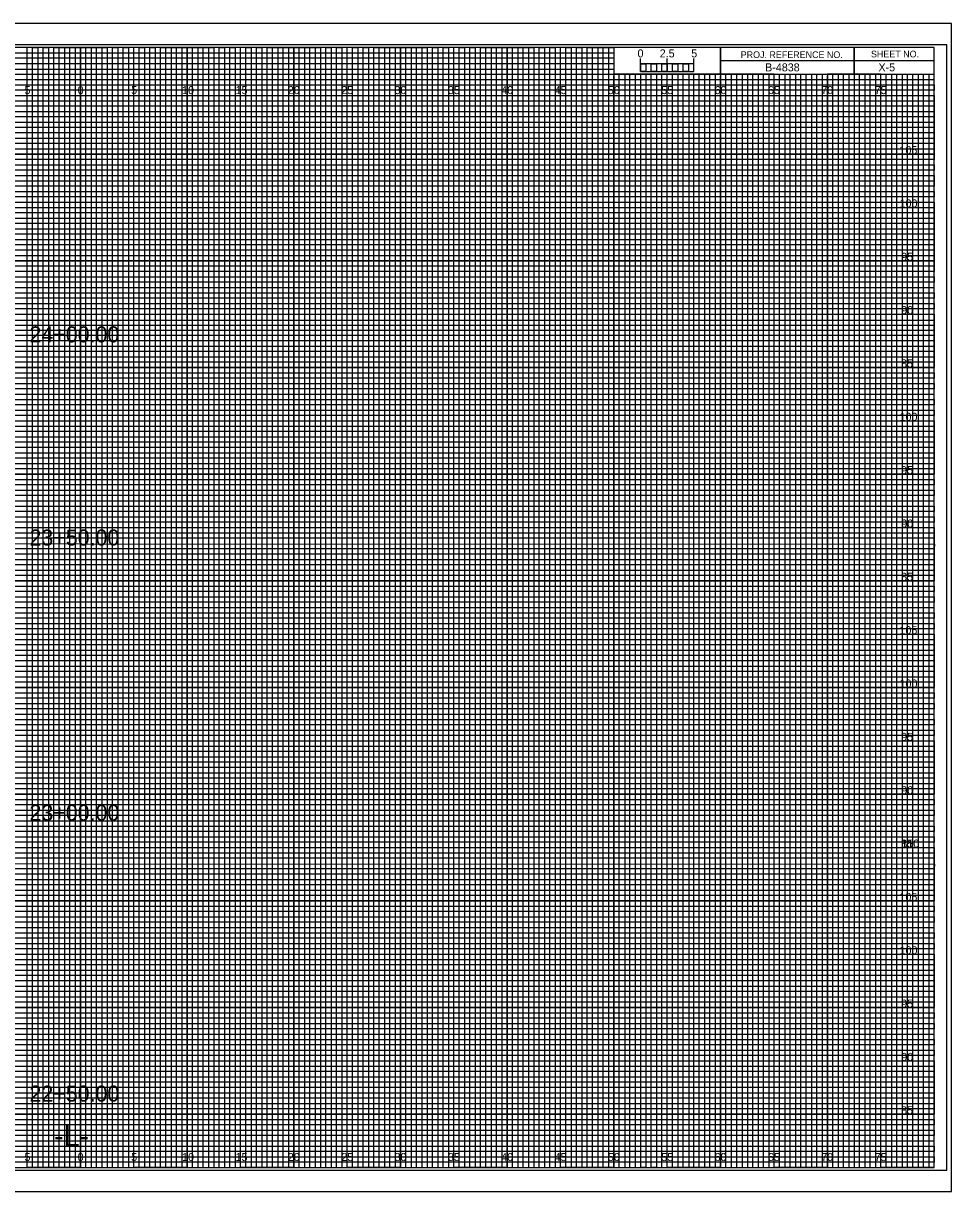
# Model space of a CAD drawing. Extents: x -7 to 182, y -2 to 1647.
# Drawn here: x 74.6 to 161.7, y 327.7 to 437.2 of the extents above; entities that cross this region are included whole.
import ezdxf

# ---------------------------------------------------------------- set-up
doc = ezdxf.new("R2010")
doc.units = 0
for name, color, linetype in [('Exist CMT Pavement', 7, 'Continuous'), ('Exist Cross Section Cell', 7, 'Continuous'), ('Exist XS Ground Line', 7, 'Continuous'), ('Prop CMT Pvmt Course 1', 7, 'Continuous'), ('Prop CMT Pvmt Course 2', 7, 'Continuous'), ('Prop CMT Pvmt Course 2 Wedge', 7, 'Continuous'), ('Prop CMT Pvmt Course 3', 7, 'Continuous'), ('Prop CMT Pvmt Surface', 7, 'Continuous'), ('Prop CMT Pvmt Surface Shoulder', 7, 'Continuous'), ('Prop CMT Pvmt Wedge Surface 1', 7, 'Continuous'), ('Prop CMT Pvmt Wedge Surface 2', 7, 'Continuous'), ('Prop CMT Pvmt Wedge Surface 3', 7, 'Continuous'), ('Prop CMT Shld Paved Course 1', 7, 'Continuous'), ('Prop CMT Shld Paved Course 2', 7, 'Continuous'), ('Prop CMT Shld Paved Course 3', 7, 'Continuous'), ('Prop CMT Slope Grass', 7, 'Continuous'), ('Prop CMT Subgrade Earthwork', 7, 'Continuous')]:
    doc.layers.add(name, color=color, linetype=linetype)

msp = doc.modelspace()

# ---------------------------------------------------------------- linework, layer by layer
at = {"layer": 'Exist XS Ground Line'}
for p, q in [((75, 435), (70, 435)), ((75, 330), (75, 435)), ((85, 435), (80, 435)), ((80, 435), (80, 330)), ((85, 330), (85, 435)), ((95, 435), (90, 435)), ((90, 435), (90, 330)), ((95, 330), (95, 435)), ((105, 435), (100, 435)), ((100, 435), (100, 330)), ((105, 330), (105, 435)), ((115, 435), (110, 435)), ((110, 435), (110, 330)), ((115, 330), (115, 435)), ((125, 435), (120, 435)), ((120, 435), (120, 330)), ((125, 330), (125, 435)), ((130, 435), (130, 330)), ((135, 330), (135, 432.5)), ((145, 432.5), (140, 432.5)), ((140, 432.5), (140, 330)), ((145, 330), (145, 432.5)), ((155, 432.5), (150, 432.5)), ((150, 432.5), (150, 330)), ((155, 330), (155, 432.5)), ((80, 330), (75, 330)), ((90, 330), (85, 330)), ((100, 330), (95, 330)), ((110, 330), (105, 330)), ((120, 330), (115, 330)), ((130, 330), (125, 330)), ((140, 330), (135, 330)), ((150, 330), (145, 330)), ((160, 330), (155, 330)), ((160, 330), (160, 330))]:
    msp.add_line(p, q, dxfattribs=at)
for points in [[(0, 430), (160, 430), (160, 425), (0, 425)], [(0, 420), (160, 420), (160, 415), (0, 415)], [(0, 410), (160, 410), (160, 405), (0, 405)], [(0, 400), (160, 400), (160, 395), (0, 395)], [(0, 390), (160, 390), (160, 385), (0, 385)], [(0, 380), (160, 380), (160, 375), (0, 375)], [(0, 370), (160, 370), (160, 365), (0, 365)], [(0, 360), (160, 360), (160, 355), (0, 355)], [(0, 350), (160, 350), (160, 345), (0, 345)], [(0, 340), (160, 340), (160, 335), (0, 335)]]:
    msp.add_lwpolyline(points, dxfattribs=at)
at = {"layer": 'Prop CMT Pvmt Course 2'}
for p, q in [((132.5, 432.75), (132.5, 433.95)), ((132.5, 433.45), (132.5, 433.95)), ((135, 432.75), (135, 433.95)), ((137.5, 432.75), (137.5, 433.95)), ((137.5, 433.45), (137.5, 433.95))]:
    msp.add_line(p, q, dxfattribs=at)
for points in [[(137.5, 433.45), (132.5, 433.45), (132.5, 432.75), (137.5, 432.75)], [(132.5, 433.45), (133, 433.45), (133, 432.75), (132.5, 432.75)], [(133.5, 433.45), (134, 433.45), (134, 432.75), (133.5, 432.75)], [(134.5, 433.45), (135, 433.45), (135, 432.75), (134.5, 432.75)], [(135.5, 433.45), (136, 433.45), (136, 432.75), (135.5, 432.75)], [(136.5, 433.45), (137, 433.45), (137, 432.75), (136.5, 432.75)]]:
    msp.add_lwpolyline(points, close=True, dxfattribs=at)
at = {"layer": 'Prop CMT Pvmt Course 3'}
msp.add_lwpolyline([(-6.7, 327.75), (161.65, 327.75), (161.65, 437.25), (-6.7, 437.25)], close=True, dxfattribs=at)
at = {"layer": 'Prop CMT Pvmt Wedge Surface 1'}
for p, q in [((0, 434.5), (130, 434.5)), ((130, 433.99), (0, 433.99)), ((130, 434.5), (130, 433.99)), ((0, 433.5), (130, 433.5)), ((130, 432.94), (0, 432.94)), ((130, 433.5), (130, 432.94)), ((0, 432), (160, 432))]:
    msp.add_line(p, q, dxfattribs=at)
for points in [[(0, 431.5), (135, 431.5), (160, 431.5), (160, 431), (0, 431)], [(0, 430.5), (160, 430.5), (160, 429.5), (0, 429.5)], [(0, 429), (160, 429), (160, 428.5), (0, 428.49)], [(0, 428), (160, 428), (160, 427), (0, 427)], [(0, 426.5), (160, 426.5), (160, 426), (0, 426)], [(0, 425.5), (160, 425.5), (160, 424.5), (0, 424.5)], [(0, 424), (160, 424), (160, 423.5), (0, 423.5)], [(0, 423), (160, 423), (160, 422), (0, 422)], [(0, 421.5), (160, 421.5), (160, 421), (0, 421)], [(0, 420.5), (160, 420.5), (160, 419.5), (0, 419.5)], [(0, 419), (160, 419), (160, 418.5), (0, 418.5)], [(0, 418), (160, 418), (160, 416.98), (160, 416.5), (160, 416), (0, 416)], [(0, 417), (160, 417), (160, 416.5), (0, 416.5)], [(0, 415.5), (160, 415.5), (160, 414.5), (0, 414.51)], [(0, 414.51), (160, 414.5), (160, 414), (0, 414)], [(0, 413.5), (160, 413.5), (160, 413), (0, 413)], [(0, 412), (160, 412), (160, 411.5), (0, 411.5)], [(0, 411), (160, 411), (160, 410.5), (0, 410.5)], [(-0.04, 409.44), (160, 409.44), (160, 408.94), (-0.04, 408.94)], [(0, 408.5), (160, 408.5), (160, 408), (0, 408)], [(0, 407), (160, 407), (160, 406.5), (0, 406.5)], [(0, 406), (160, 406), (160, 405.5), (0, 405.5)], [(0, 404.5), (160, 404.5), (160, 404), (0, 404)], [(0, 403.5), (160, 403.5), (160, 403), (0, 403)], [(0, 402), (160, 402), (160, 401.5), (0, 401.5)], [(0, 401), (160, 401), (160, 400.5), (0, 400.5)], [(0, 399.5), (160, 399.5), (160, 398.99), (0, 399)], [(0, 398.5), (160, 398.5), (160, 398), (0, 398)], [(0, 397), (160, 397), (160, 396.5), (0, 396.5)], [(0, 396), (160, 396), (160, 395.5), (0, 395.5)], [(0, 394.5), (160, 394.5), (160, 394), (0, 394)], [(0, 393.5), (160, 393.5), (160, 393), (0, 393)], [(0, 392), (160, 392), (160, 391.5), (0, 391.5)], [(0, 391), (160, 391), (160, 390.5), (0, 390.5)], [(0, 389.5), (160, 389.5), (160, 389), (0, 389)], [(0, 388.5), (160.03, 388.45), (160, 388), (0, 388)], [(0, 387), (160, 387), (160, 386.5), (0, 386.5)], [(0, 386), (160, 386), (160, 385.5), (0, 385.5)], [(0, 384.5), (160, 384.5), (160, 384), (0, 384)], [(0, 383.5), (160, 383.5), (160, 383), (0, 383)], [(0, 382), (160, 382), (160, 381.5), (0, 381.5)], [(0, 381), (160, 381), (160, 380.5), (0, 380.5)], [(0, 379.5), (160, 379.5), (160, 379), (0, 379)], [(0, 378.5), (160, 378.5), (160, 378), (0, 378)], [(0, 377), (160, 377), (160, 376.5), (0, 376.5)], [(0, 376), (160, 376), (160, 375.5), (0, 375.5)], [(0, 374.5), (160, 374.5), (160, 374), (0, 374)], [(0, 373.5), (160, 373.5), (160, 373), (0, 373)], [(0, 372), (160, 372), (160, 371.5), (0, 371.5)], [(0, 371), (160, 371), (160, 370.5), (0, 370.5)], [(0, 369.5), (160, 369.5), (160, 368.99), (0, 369)], [(0, 368.5), (160, 368.5), (160, 368), (0, 368)], [(0, 367), (160, 367), (160, 366.5), (0, 366.5)], [(0, 366), (160, 366), (160, 365.5), (0, 365.5)], [(0, 364.5), (160, 364.5), (160, 364), (0, 364)], [(0, 363.5), (160, 363.5), (160, 363), (0, 363)], [(0, 362), (160, 362), (160, 361.5), (0, 361.5)], [(0, 361), (160, 361), (160, 360.5), (0, 360.5)], [(0, 359.5), (160, 359.5), (160, 359), (0, 359)], [(0, 358.5), (160.03, 358.45), (160, 358), (0, 358)], [(0, 357), (160, 357), (160, 356.5), (0, 356.5)], [(0, 356), (160, 356), (160, 355.5), (0, 355.5)], [(0, 354.5), (160, 354.5), (160, 354), (0, 354)], [(0, 353.5), (160, 353.5), (160, 353), (0, 353)], [(0, 352), (160, 352), (160, 351.5), (0, 351.5)], [(0, 351), (160, 351), (160, 350.5), (0, 350.5)], [(0, 349.5), (160, 349.5), (160, 349), (0, 349)], [(0, 348.5), (160, 348.5), (160, 348), (0, 348)], [(0, 347), (160, 347), (160, 346.5), (0, 346.5)], [(0, 346), (160, 346), (160, 345.5), (0, 345.5)], [(0, 344.5), (160, 344.5), (160, 344), (0, 344)], [(0, 343.5), (160, 343.5), (160, 343), (0, 343)], [(0, 342), (160, 342), (160, 341.5), (0, 341.5)], [(0, 341), (160, 341), (160, 340.5), (0, 340.5)], [(0, 339.5), (160, 339.5), (160, 339), (0, 339)], [(0, 338.5), (160, 338.5), (160, 338), (0, 338)], [(0, 337), (160, 337), (160, 336.5), (0, 336.5)], [(0, 336), (160, 336), (160, 335.5), (0, 335.5)], [(0, 334.5), (160, 334.5), (160, 334), (0, 334)], [(0, 333.5), (160, 333.5), (160, 333), (0, 333)], [(0, 332), (160, 332), (160, 331.5), (0, 331.5)], [(0, 331), (160, 331), (160, 330.5), (0, 330.5)]]:
    msp.add_lwpolyline(points, dxfattribs=at)
at = {"layer": 'Prop CMT Pvmt Wedge Surface 2'}
for p, q in [((152.5, 435), (152.5, 432.5)), ((152.5, 432.5), (152.5, 435)), ((160, 433.75), (140, 433.75)), ((140, 433.75), (140, 432.5)), ((140, 432.5), (160, 432.5))]:
    msp.add_line(p, q, dxfattribs=at)
for points in [[(160, 435), (0, 435), (0, 330), (160, 330)], [(140, 435), (130, 435), (130, 432.51), (140, 432.51)], [(160, 435), (140, 435), (140, 432.5), (160, 432.5)]]:
    msp.add_lwpolyline(points, close=True, dxfattribs=at)
at = {"layer": 'Prop CMT Pvmt Wedge Surface 3'}
for p, q in [((133.5, 432.5), (133, 432.5)), ((133, 432.5), (133, 330)), ((133.5, 330), (133.5, 432.5)), ((134.5, 432.5), (134, 432.5)), ((134, 432.5), (134, 330)), ((134.5, 330), (134.5, 432.5)), ((133, 330), (132.5, 330)), ((134, 330), (133.5, 330))]:
    msp.add_line(p, q, dxfattribs=at)
for points in [[(75, 330), (75.5, 330), (75.5, 435), (76, 435), (76, 330)], [(76, 330), (76.5, 330), (76.5, 435), (77, 435), (77, 330)], [(77.5, 330), (78, 330), (78, 435), (78.5, 435), (78.5, 330)], [(78.5, 330), (79, 330), (79, 435), (79.5, 435), (79.5, 330)], [(80, 330), (80.5, 330), (80.5, 435), (81, 435), (81, 330)], [(81, 330), (81.5, 330), (81.5, 435), (82, 435), (82, 330)], [(82.5, 330), (83, 330), (83, 435), (83.5, 435), (83.5, 330)], [(83.5, 330), (84, 330), (84, 435), (84.5, 435), (84.5, 330)], [(85, 330), (85.5, 330), (85.5, 435), (86, 435), (86, 330)], [(86, 330), (86.5, 330), (86.5, 435), (87, 435), (87, 330)], [(87.5, 330), (88, 330), (88, 435), (88.5, 435), (88.5, 330)], [(88.5, 330), (89, 330), (89, 435), (89.5, 435), (89.5, 330)], [(90, 330), (90.5, 330), (90.5, 435), (91, 435), (91, 330)], [(91, 330), (91.5, 330), (91.5, 435), (92, 435), (92, 330)], [(92.5, 330), (93, 330), (93, 435), (93.5, 435), (93.5, 330)], [(93.5, 330), (94, 330), (94, 435), (94.5, 435), (94.5, 330)], [(95, 330), (95.5, 330), (95.5, 435), (96, 435), (96, 330)], [(96, 330), (96.5, 330), (96.5, 435), (97, 435), (97, 330)], [(97.5, 330), (98, 330), (98, 435), (98.5, 435), (98.5, 330)], [(98.5, 330), (99, 330), (99, 435), (99.5, 435), (99.5, 330)], [(100, 330), (100.5, 330), (100.5, 435), (101, 435), (101, 330)], [(101, 330), (101.5, 330), (101.5, 435), (102, 435), (102, 330)], [(102.5, 330), (103, 330), (103, 435), (103.5, 435), (103.5, 330)], [(103.5, 330), (104, 330), (104, 435), (104.5, 435), (104.5, 330)], [(105, 330), (105.5, 330), (105.5, 435), (106, 435), (106, 330)], [(106, 330), (106.5, 330), (106.5, 435), (107, 435), (107, 330)], [(107.5, 330), (108, 330), (108, 435), (108.5, 435), (108.5, 330)], [(108.5, 330), (109, 330), (109, 435), (109.5, 435), (109.5, 330)], [(110, 330), (110.5, 330), (110.5, 435), (111, 435), (111, 330)], [(111, 330), (111.5, 330), (111.5, 435), (112, 435), (112, 330)], [(112.5, 330), (113, 330), (113, 435), (113.5, 435), (113.5, 330)], [(113.5, 330), (114, 330), (114, 435), (114.5, 435), (114.5, 330)], [(115, 330), (115.5, 330), (115.5, 435), (116, 435), (116, 330)], [(116, 330), (116.5, 330), (116.5, 435), (117, 435), (117, 330)], [(117.5, 330), (118, 330), (118, 435), (118.5, 435), (118.5, 330)], [(118.5, 330), (119, 330), (119, 435), (119.5, 435), (119.5, 330)], [(120, 330), (120.5, 330), (120.5, 435), (121, 435), (121, 330)], [(121, 330), (121.5, 330), (121.5, 435), (122, 435), (122, 330)], [(122.5, 330), (123, 330), (123, 435), (123.5, 435), (123.5, 330)], [(123.5, 330), (124, 330), (124, 435), (124.5, 435), (124.5, 330)], [(125, 330), (125.5, 330), (125.5, 435), (126, 435), (126, 330)], [(126, 330), (126.5, 330), (126.5, 435), (127, 435), (127, 330)], [(127.5, 330), (128, 330), (128, 435), (128.5, 435), (128.5, 330)], [(128.5, 330), (129, 330), (129, 435), (129.5, 435), (129.5, 330)], [(130, 330), (130.5, 330), (130.5, 432.5), (131.01, 432.5), (131.01, 330)], [(131, 330), (131.5, 330), (131.5, 432.5), (132, 432.5), (132, 330)], [(135, 330), (135.49, 330), (135.49, 432.5), (136, 432.5), (136, 330)], [(136, 330), (136.5, 330), (136.5, 432.5), (137.03, 432.5), (137.03, 330)], [(137.5, 330), (138, 330), (138, 432.5), (138.5, 432.5), (138.5, 330)], [(138.5, 330), (139, 330), (139, 432.5), (139.5, 432.5), (139.5, 330)], [(140, 330), (140.5, 330), (140.5, 432.5), (141, 432.5), (141, 330)], [(141, 330), (141.5, 330), (141.5, 432.5), (142, 432.5), (142, 330)], [(142.5, 330), (143, 330), (143, 432.5), (143.5, 432.5), (143.5, 330)], [(143.5, 330), (144, 330), (144, 432.5), (144.5, 432.5), (144.5, 330)], [(145, 330), (145.5, 330), (145.5, 432.5), (146, 432.5), (146, 330)], [(146, 330), (146.5, 330), (146.5, 432.5), (147, 432.5), (147, 330)], [(147.5, 330), (148, 330), (148, 432.5), (148.5, 432.5), (148.5, 330)], [(148.5, 330), (149, 330), (149, 432.5), (149.5, 432.5), (149.5, 330)], [(150, 330), (150.5, 330), (150.5, 432.5), (151, 432.5), (151, 330)], [(151, 330), (151.5, 330), (151.5, 432.5), (152, 432.5), (152, 330)], [(152.5, 330), (153, 330), (153, 432.5), (153.5, 432.5), (153.5, 330)], [(153.5, 330), (154, 330), (154, 432.5), (154.5, 432.5), (154.5, 330)], [(155, 330), (155.5, 330), (155.5, 432.5), (156, 432.5), (156, 330)], [(156, 330), (156.5, 330), (156.5, 432.5), (157, 432.5), (157, 330)], [(157.5, 330), (158, 330), (158, 432.5), (158.5, 432.5), (158.5, 330)], [(158.5, 330), (159, 330), (159, 432.5), (159.5, 432.5), (159.5, 330)]]:
    msp.add_lwpolyline(points, dxfattribs=at)
at = {"layer": 'Prop CMT Shld Paved Course 1'}
for p, q in [((75, 330), (75, 435)), ((80, 330), (80, 435)), ((85, 330), (85, 435)), ((90, 330), (90, 435)), ((95, 330), (95, 435)), ((100, 330), (100, 435)), ((105, 330), (105, 435)), ((110, 330), (110, 435)), ((115, 330), (115, 435)), ((120, 330), (120, 435)), ((125, 330), (125, 435)), ((130, 330), (130, 432.34)), ((135, 330), (135, 432.34)), ((140, 330), (140, 432.34)), ((145, 330), (145, 432.34)), ((150, 330), (150, 432.34)), ((155, 330), (155, 432.34)), ((0, 430), (160, 430)), ((0, 425), (160, 425)), ((0, 420), (160, 420)), ((0, 415), (160, 415)), ((0, 410), (160, 410)), ((0, 405), (160, 405)), ((0, 400), (160, 400)), ((0, 395), (160, 395)), ((0, 390), (160, 390)), ((0, 385), (160, 385)), ((0, 380), (160, 380)), ((0, 375), (160, 375)), ((0, 370), (160, 370)), ((0, 365), (160, 365)), ((0, 360), (160, 360)), ((0, 355), (160, 355)), ((0, 350), (160, 350)), ((0, 345), (160, 345)), ((0, 340), (160, 340)), ((0, 335), (160, 335))]:
    msp.add_line(p, q, dxfattribs=at)
at = {"layer": 'Prop CMT Shld Paved Course 2'}
for p, q in [((161.65, 437.25), (-6.7, 437.25)), ((-6.7, 327.75), (161.65, 327.75))]:
    msp.add_line(p, q, dxfattribs=at)
at = {"layer": 'Prop CMT Slope Grass'}
msp.add_lwpolyline([(-5.4, 329.75), (161.2, 329.75), (161.2, 435.25), (-5.4, 435.25)], close=True, dxfattribs=at)
at = {"layer": 'Prop CMT Subgrade Earthwork'}
for points in [[(72.5, 330), (77.5, 330), (77.5, 435), (82.5, 435), (82.5, 330), (87.5, 330), (87.5, 435), (92.5, 435), (92.5, 330), (97.5, 330), (97.5, 435), (102.5, 435), (102.5, 330), (107.5, 330), (107.5, 435), (112.5, 435), (112.5, 330), (117.5, 330), (117.5, 435), (122.5, 435), (122.5, 330), (127.5, 330), (127.5, 435), (129.97, 435), (130, 435), (130, 432.5), (132.5, 432.5), (132.5, 330), (137.5, 330), (137.5, 432.5), (142.5, 432.5), (142.5, 330), (147.5, 330), (147.5, 432.5), (152.5, 432.5), (152.5, 330), (157.5, 330), (157.5, 432.5)], [(0, 432.5), (137.5, 432.5)], [(0, 422.5), (160, 422.5), (160, 427.5), (0, 427.5)], [(0, 412.5), (160, 412.5), (160, 417.5), (0, 417.5)], [(0, 402.5), (160, 402.5), (160, 407.5), (0, 407.5)], [(0, 392.5), (160, 392.5), (160, 397.5), (0, 397.5)], [(0, 382.5), (160, 382.5), (160, 387.5), (0, 387.5)], [(0, 372.5), (160, 372.5), (160, 377.5), (0, 377.5)], [(0, 362.5), (160, 362.5), (160, 367.5), (0, 367.5)], [(0, 352.5), (160, 352.5), (160, 357.5), (0, 357.5)], [(0, 342.5), (160, 342.5), (160, 347.5), (0, 347.5)], [(0, 332.5), (160, 332.5), (160, 337.5), (0, 337.5)]]:
    msp.add_lwpolyline(points, dxfattribs=at)

# ---------------------------------------------------------------- texts
at = {"layer": 'Exist CMT Pavement'}
for s, p in [('24+00.00', (75.21, 407.35)), ('23+50.00', (75.21, 388.31)), ('23+00.00', (75.21, 362.52)), ('22+50.00', (75.21, 336.19))]:
    msp.add_text(s, height=1.5, dxfattribs=at).set_placement(p)
at = {"layer": 'Exist Cross Section Cell'}
for s, p in [('5', (74.74, 430.62)), ('0', (79.73, 430.62)), ('0', (79.73, 430.62)), ('5', (84.74, 430.62)), ('10', (89.52, 430.62)), ('15', (94.53, 430.62)), ('20', (99.43, 430.62)), ('25', (104.44, 430.62)), ('30', (109.43, 430.62)), ('35', (114.44, 430.62)), ('40', (119.43, 430.62)), ('45', (124.44, 430.62)), ('50', (129.43, 430.62)), ('55', (134.44, 430.62)), ('60', (139.43, 430.62)), ('65', (144.44, 430.62)), ('70', (149.43, 430.62)), ('75', (154.44, 430.62)), ('5', (74.74, 330.62)), ('0', (79.73, 330.62)), ('0', (79.73, 330.62)), ('5', (84.74, 330.62)), ('10', (89.52, 330.62)), ('15', (94.53, 330.62)), ('20', (99.43, 330.62)), ('25', (104.44, 330.62)), ('30', (109.43, 330.62)), ('35', (114.44, 330.62)), ('40', (119.43, 330.62)), ('45', (124.44, 330.62)), ('50', (129.43, 330.62)), ('55', (134.44, 330.62)), ('60', (139.43, 330.62)), ('65', (144.44, 330.62)), ('70', (149.43, 330.62)), ('75', (154.44, 330.62))]:
    msp.add_text(s, height=0.75, dxfattribs=at).set_placement(p)
at = {"layer": 'Prop CMT Pvmt Course 1'}
msp.add_text('-L-', height=2, dxfattribs=at).set_placement((77.53, 332))
at = {"layer": 'Prop CMT Pvmt Course 2'}
msp.add_text('0', height=0.75, dxfattribs=at).set_placement((132.21, 434.06))
at = {"layer": 'Prop CMT Pvmt Course 2 Wedge'}
for s, p in [('2.5', (134.29, 434.06)), ('5', (137.24, 434.06))]:
    msp.add_text(s, height=0.75, dxfattribs=at).set_placement(p)
at = {"layer": 'Prop CMT Pvmt Surface'}
msp.add_text('X-5', height=0.75, dxfattribs=at).set_placement((154.79, 432.75))
at = {"layer": 'Prop CMT Pvmt Surface Shoulder'}
msp.add_text('B-4838', height=0.75, dxfattribs=at).set_placement((144.17, 432.75))
at = {"layer": 'Prop CMT Pvmt Wedge Surface 2'}
for s, p in [('PROJ. REFERENCE NO.', (141.88, 434)), ('SHEET NO.', (154.09, 434.06))]:
    msp.add_text(s, height=0.625, dxfattribs=at).set_placement(p)
at = {"layer": 'Prop CMT Shld Paved Course 3'}
for s, p in [('105', (156.76, 425)), ('100', (156.77, 420)), ('95', (156.92, 415)), ('90', (156.93, 410)), ('85', (156.91, 405)), ('100', (156.77, 400)), ('95', (156.92, 395)), ('90', (156.93, 390)), ('85', (156.91, 385)), ('105', (156.76, 380)), ('100', (156.77, 375)), ('95', (156.92, 370)), ('90', (156.93, 365)), ('85', (156.91, 360)), ('110', (156.94, 360)), ('105', (156.76, 355)), ('100', (156.77, 350)), ('95', (156.92, 345)), ('90', (156.93, 340)), ('85', (156.91, 335))]:
    msp.add_text(s, height=0.75, dxfattribs=at).set_placement(p)

doc.saveas('drawing.dxf')
